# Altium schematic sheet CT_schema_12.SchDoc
size 389 x 278 mm
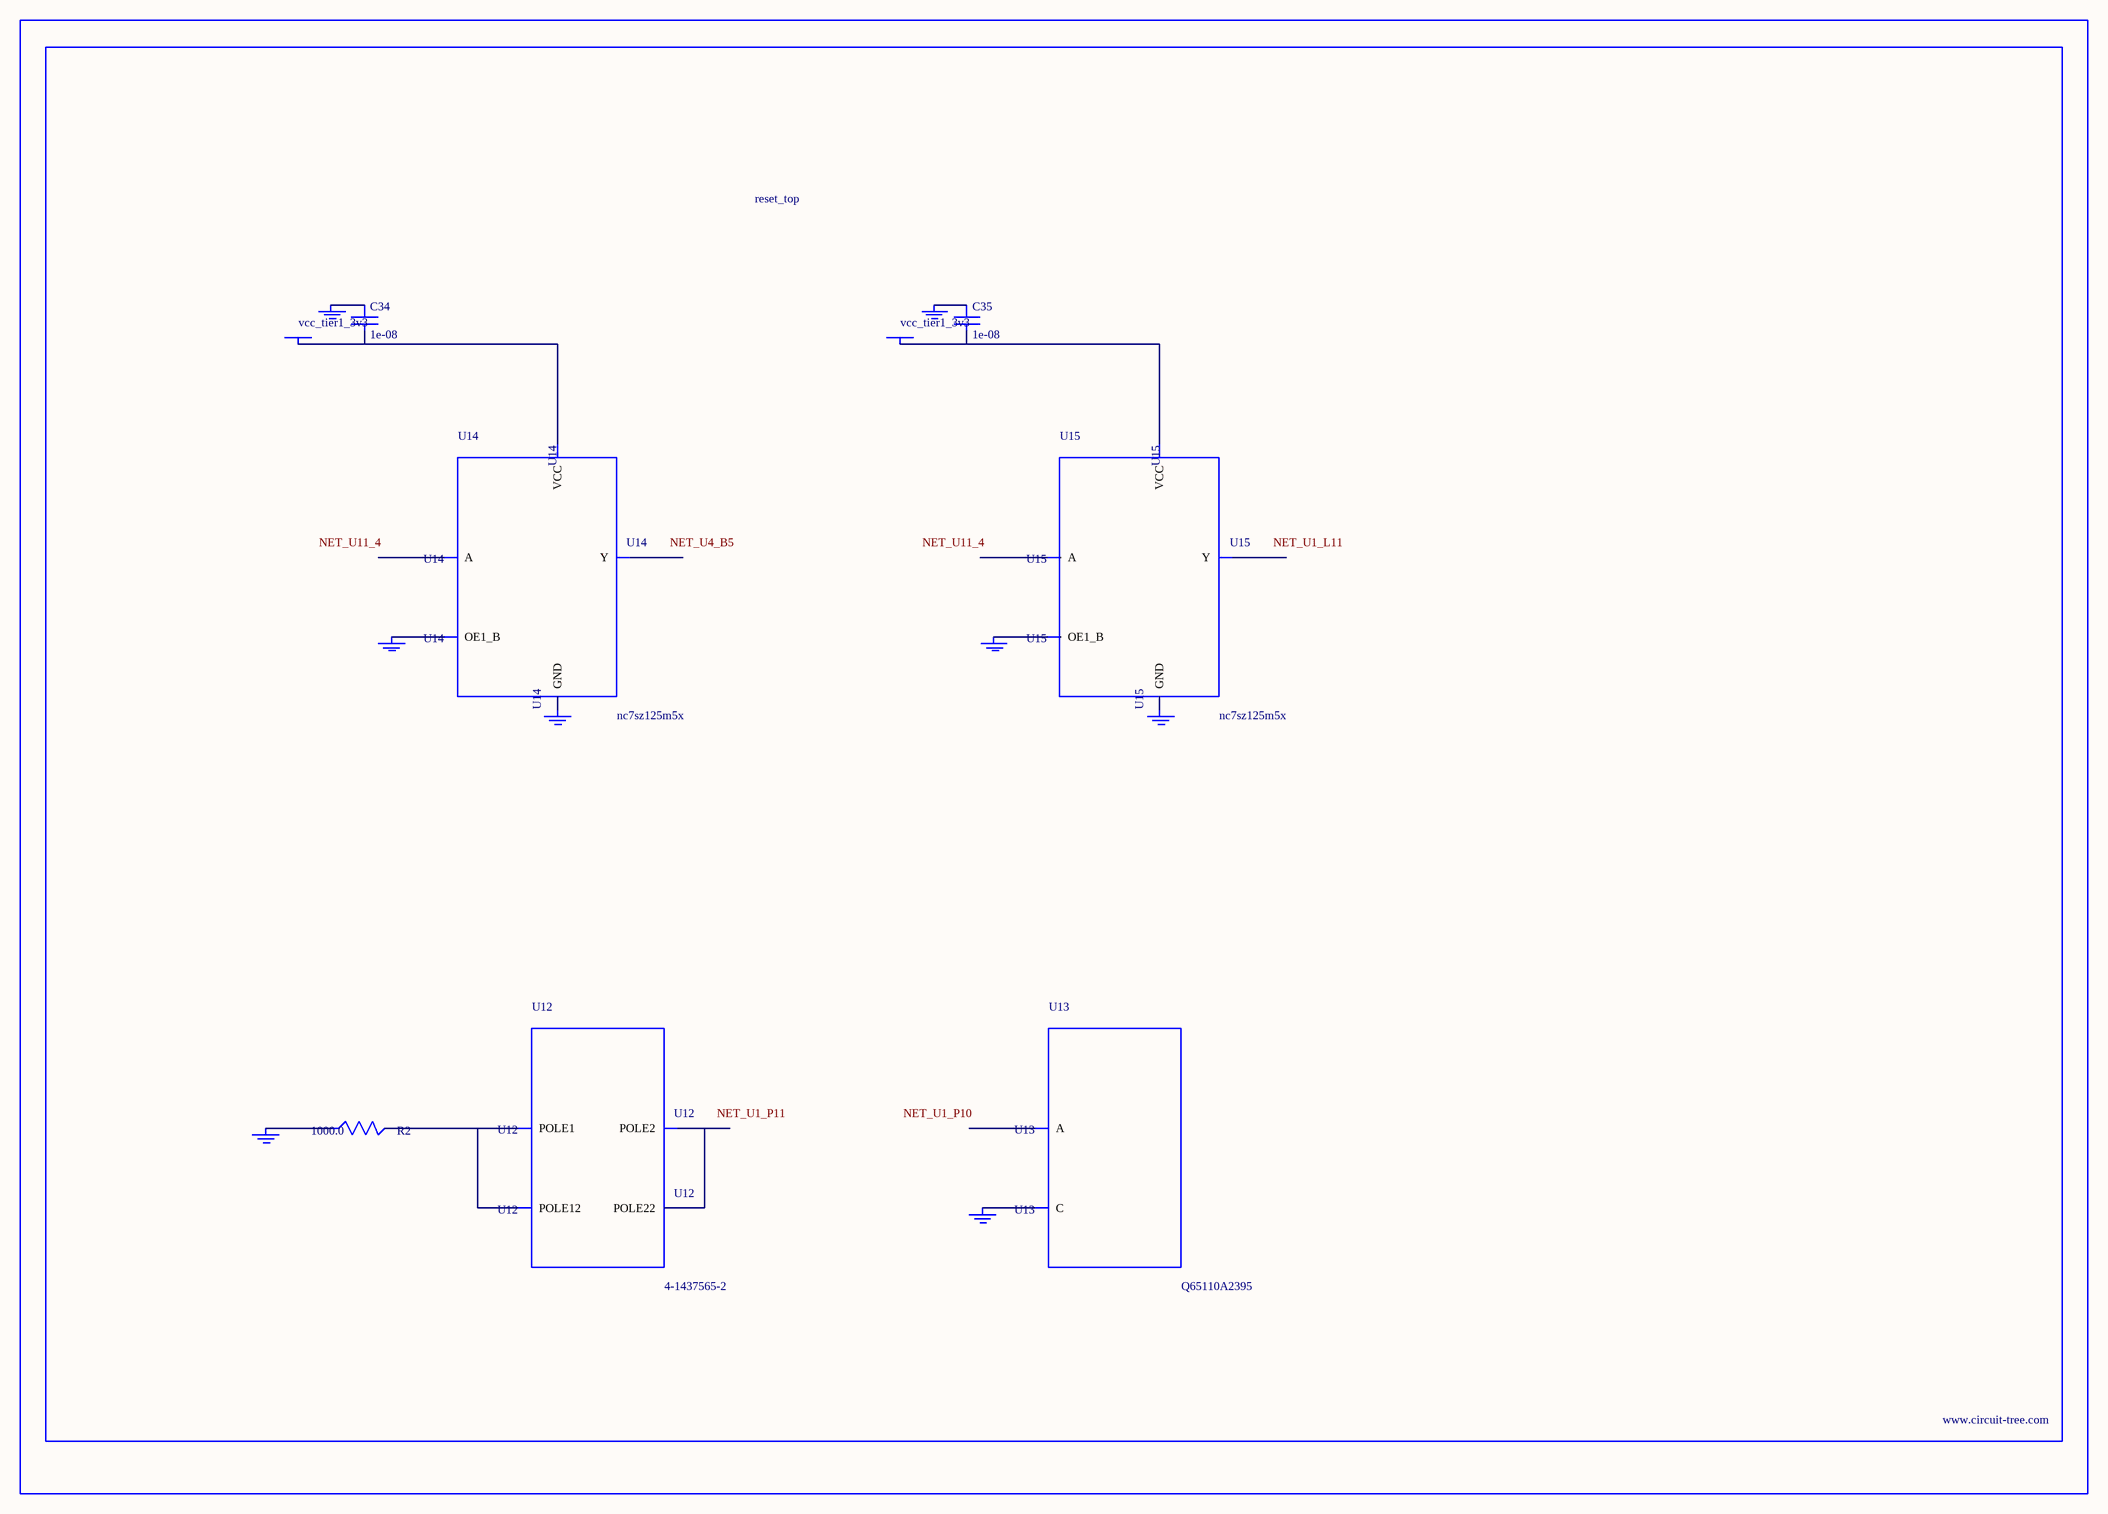
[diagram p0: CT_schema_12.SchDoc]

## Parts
BORDER11  (no value)
C34  1e-08  [C0402]
C35  1e-08  [C0402]
GND_INSTANCE_11_0  (no value)
GND_INSTANCE_11_1  (no value)
GND_INSTANCE_11_2  (no value)
GND_INSTANCE_11_3  (no value)
GND_INSTANCE_11_4  (no value)
GND_INSTANCE_11_5  (no value)
GND_INSTANCE_11_6  (no value)
GND_INSTANCE_11_7  (no value)
POWER_INSTANCE_11_0  vcc_tier1_3v3
POWER_INSTANCE_11_1  vcc_tier1_3v3
R2  1000.0  [R0603]
U12  4-1437565-2  [SW_4-1437565-2]
U13  Q65110A2395  [LGM67K-G1J2-24-Z]
U14  nc7sz125m5x  [NC7SZ125M5X]
U15  nc7sz125m5x  [NC7SZ125M5X]

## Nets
NetC34_1: C34.1 GND_INSTANCE_11_2.0(GND)
NetC34_2: C34.2 POWER_INSTANCE_11_0.0(PWR) U14.5(VCC)
NetC35_1: C35.1 GND_INSTANCE_11_5.0(GND)
NetC35_2: C35.2 POWER_INSTANCE_11_1.0(PWR) U15.5(VCC)
NetGND_INSTANCE_11_0_0: GND_INSTANCE_11_0.0(GND) R2.1
NetGND_INSTANCE_11_1_0: GND_INSTANCE_11_1.0(GND) U13.C
NetGND_INSTANCE_11_3_0: GND_INSTANCE_11_3.0(GND) U14.1(OE1_B)
NetGND_INSTANCE_11_4_0: GND_INSTANCE_11_4.0(GND) U14.3(GND)
NetGND_INSTANCE_11_6_0: GND_INSTANCE_11_6.0(GND) U15.1(OE1_B)
NetGND_INSTANCE_11_7_0: GND_INSTANCE_11_7.0(GND) U15.3(GND)
NetR2_2: R2.2 U12.1(POLE1) U12.2(POLE12)
NetU12_3: U12.3(POLE2) U12.4(POLE22)

Not connected (* = marked no-connect by the designer): U13 A; U14 2(A) 4(Y); U15 2(A) 4(Y)

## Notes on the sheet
- Labels drawn without touching a wire or pin: NET_U1_L11, NET_U1_P10, NET_U1_P11, NET_U4_B5, NET_U11_4

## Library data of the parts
BORDER11 = BORDER_PAGE11
C34 C35 = C0402C103K3RAC
GND_INSTANCE_11_0-GND_INSTANCE_11_7 = GND
POWER_INSTANCE_11_0 POWER_INSTANCE_11_1 = PWR
R2 = RC0603JR-071KL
